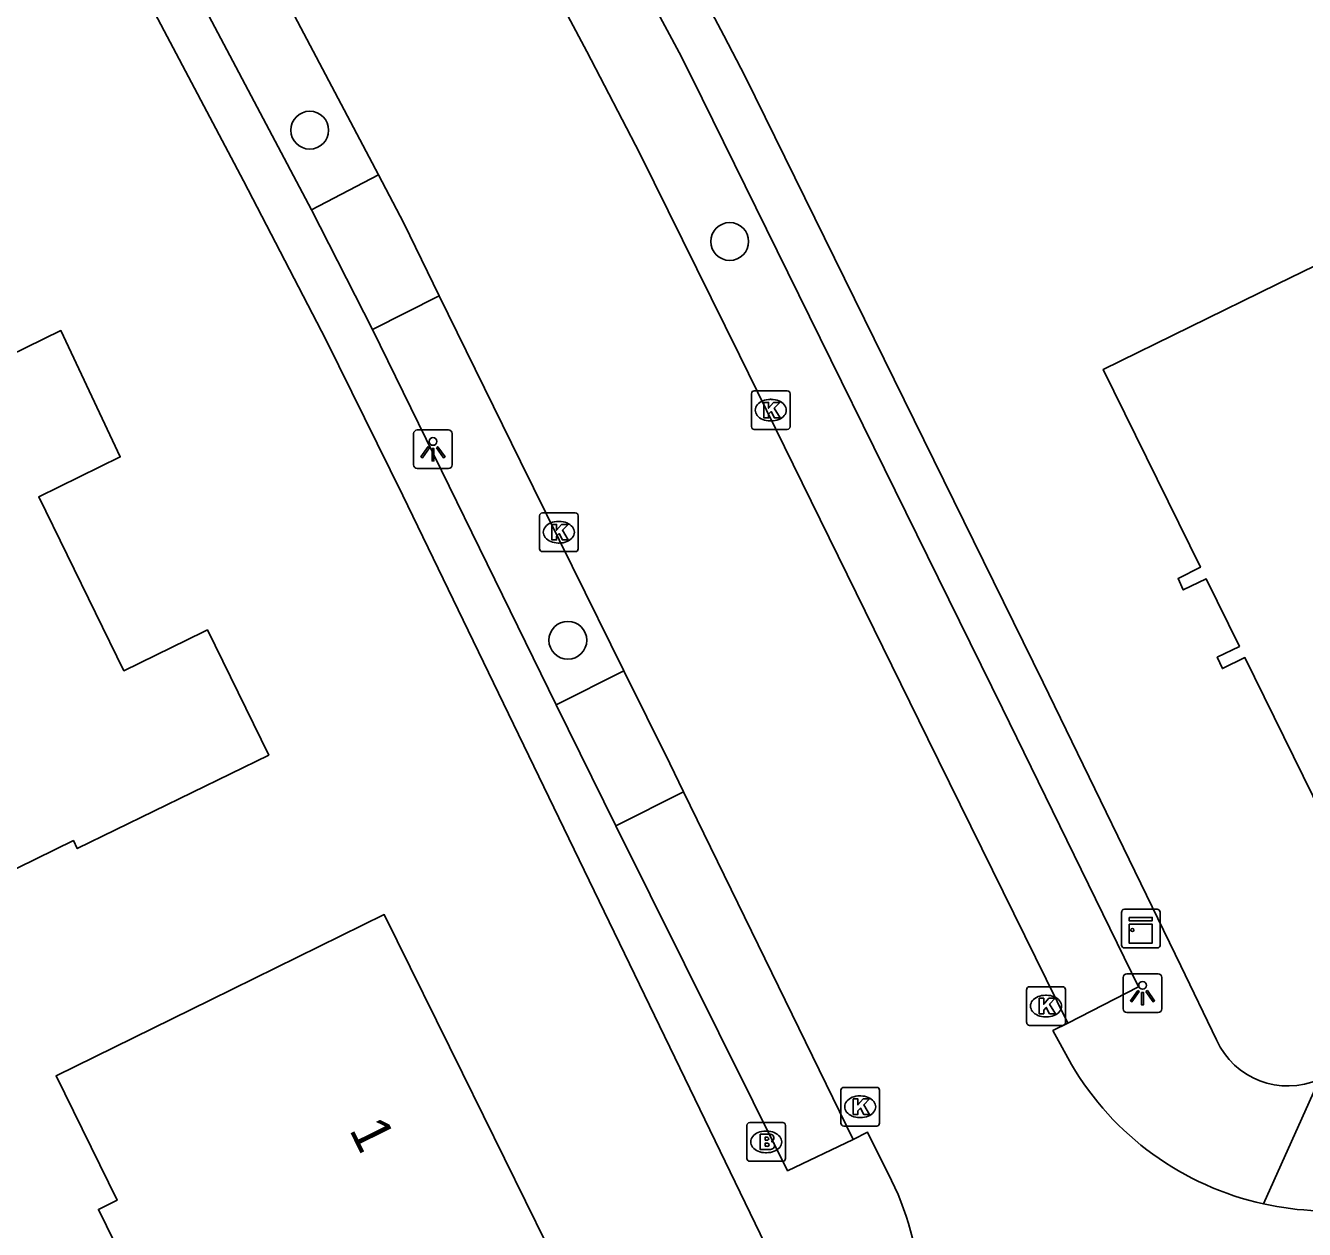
# Model space of a CAD drawing. Extents: x 160457 to 162082, y 388340 to 389736.
# Drawn here: x 160695.95 to 160729, y 389050.96 to 389082.07 of the extents above; entities that cross this region are included whole.
import ezdxf

# ---------------------------------------------------------------- set-up
doc = ezdxf.new("R2010")
doc.units = 0
for name, color, linetype in [('IMGEO_Boom', 7, 'Continuous'), ('IMGEO_Brandkraan', 7, 'Continuous'), ('IMGEO_Kast', 7, 'Continuous'), ('IMGEO_Kolk', 7, 'Continuous'), ('IMGEO_Lichtpunt', 7, 'Continuous'), ('IMGEO_Pand', 7, 'Continuous'), ('IMGEO_Pand_nummerreeks', 7, 'Continuous'), ('IMGEO_Rijbaan_lokaal_gesloten', 7, 'Continuous'), ('IMGEO_Voetpad_open', 7, 'Continuous')]:
    doc.layers.add(name, color=color, linetype=linetype)

msp = doc.modelspace()

# ---------------------------------------------------------------- linework, layer by layer
at = {"layer": 'IMGEO_Boom'}
for centre in [(160703.291, 389079.364), (160714.145, 389076.488), (160709.962, 389066.184)]:
    msp.add_circle(centre, 0.489, dxfattribs=at)
at = {"layer": 'IMGEO_Brandkraan'}
for p, q in [((160714.587, 389052.796), (160714.587, 389053.648)), ((160714.662, 389053.722), (160715.514, 389053.722)), ((160715.075, 389053.502), (160715.1, 389053.502)), ((160715.588, 389053.648), (160715.588, 389052.796)), ((160715.098, 389052.942), (160715.073, 389052.942)), ((160715.514, 389052.722), (160714.662, 389052.722))]:
    msp.add_line(p, q, dxfattribs=at)
for points in [[(160714.587, 389052.796), (160714.587, 389053.648)], [(160714.662, 389053.722), (160715.514, 389053.722)], [(160715.588, 389053.648), (160715.588, 389052.796)], [(160714.935, 389053.422), (160714.935, 389053.022), (160715.148, 389053.022)], [(160715.166, 389053.422), (160714.935, 389053.422)], [(160715.114, 389053.341), (160715.06, 389053.341), (160715.06, 389053.265)], [(160715.06, 389053.265), (160715.113, 389053.265)], [(160715.122, 389053.189), (160715.06, 389053.189), (160715.06, 389053.108)], [(160715.06, 389053.108), (160715.122, 389053.108)], [(160715.514, 389052.722), (160714.662, 389052.722)]]:
    msp.add_lwpolyline(points, dxfattribs=at)
for centre, radius, start, end in [((160714.664, 389053.646), 0.0765, 91.552, 178.448), ((160714.664, 389053.646), 0.0765, 91.552, 178.448), ((160715.512, 389053.646), 0.0765, 1.552, 88.448), ((160715.512, 389053.646), 0.0765, 1.552, 88.448), ((160715.115, 389053.303), 0.0379, 267.8285, 90.9355), ((160715.123, 389053.148), 0.0404, 269.8759, 90.5077), ((160715.17, 389053.277), 0.145, 59.4692, 91.5367), ((160715.195, 389053.324), 0.0922, 285.5137, 58.1501), ((160715.2, 389053.132), 0.105, 301.3115, 78.989), ((160715.154, 389053.273), 0.251, 268.6676, 293.5347), ((160714.664, 389052.798), 0.0765, 181.552, 268.448), ((160714.664, 389052.798), 0.0765, 181.552, 268.448), ((160715.512, 389052.798), 0.0765, 271.552, 358.448), ((160715.512, 389052.798), 0.0765, 271.552, 358.448)]:
    msp.add_arc(centre, radius, start, end, dxfattribs=at)
for centre, major_axis, ratio, start_param, end_param in [((160715.074, 389053.222), (-0.387, 0.002), 0.722429, 4.712389, 7.853982), ((160715.099, 389053.222), (-0.39, 0.002), 0.717154, 1.570796, 4.712389)]:
    msp.add_ellipse(centre, major_axis=major_axis, ratio=ratio, start_param=start_param, end_param=end_param, dxfattribs=at)
at = {"layer": 'IMGEO_Kast'}
for p, q in [((160724.272, 389058.308), (160724.272, 389059.149)), ((160724.272, 389059.149), (160724.272, 389058.308)), ((160724.347, 389059.233), (160725.188, 389059.233)), ((160725.188, 389059.233), (160724.347, 389059.233)), ((160725.272, 389059.158), (160725.272, 389058.317)), ((160725.272, 389058.317), (160725.272, 389059.158)), ((160725.197, 389058.233), (160724.356, 389058.233)), ((160724.356, 389058.233), (160725.197, 389058.233))]:
    msp.add_line(p, q, dxfattribs=at)
for points in [[(160724.467, 389059.023), (160725.067, 389059.023), (160725.067, 389058.938), (160724.467, 389058.938), (160724.467, 389059.023)], [(160724.467, 389058.848), (160725.067, 389058.848), (160725.067, 389058.359), (160724.467, 389058.359), (160724.467, 389058.848)]]:
    msp.add_lwpolyline(points, dxfattribs=at)
msp.add_circle((160724.551, 389058.697), 0.0377, dxfattribs=at)
for centre, start, end in [((160724.35, 389059.155), 92.4484, 184.2845), ((160724.35, 389059.155), 92.4484, 184.2845), ((160725.194, 389059.155), 2.4484, 94.2845), ((160725.194, 389059.155), 2.4484, 94.2845), ((160724.35, 389058.311), 182.4484, 274.2845), ((160724.35, 389058.311), 182.4484, 274.2845), ((160725.194, 389058.311), 272.4484, 4.2845), ((160725.194, 389058.311), 272.4484, 4.2845)]:
    msp.add_arc(centre, 0.0779, start, end, dxfattribs=at)
at = {"layer": 'IMGEO_Kolk'}
for p, q in [((160714.706, 389071.704), (160714.706, 389072.556)), ((160714.781, 389072.63), (160715.633, 389072.63)), ((160715.194, 389072.41), (160715.219, 389072.41)), ((160715.707, 389072.556), (160715.707, 389071.704)), ((160715.217, 389071.85), (160715.192, 389071.85)), ((160715.633, 389071.63), (160714.781, 389071.63)), ((160709.228, 389068.55), (160709.228, 389069.402)), ((160709.303, 389069.476), (160710.155, 389069.476)), ((160710.229, 389069.402), (160710.229, 389068.55)), ((160709.716, 389069.256), (160709.741, 389069.256)), ((160709.739, 389068.696), (160709.714, 389068.696)), ((160710.155, 389068.476), (160709.303, 389068.476)), ((160721.819, 389056.306), (160721.819, 389057.158)), ((160721.894, 389057.232), (160722.746, 389057.232)), ((160722.82, 389057.158), (160722.82, 389056.306)), ((160722.307, 389057.012), (160722.332, 389057.012)), ((160722.33, 389056.452), (160722.305, 389056.452)), ((160722.746, 389056.232), (160721.894, 389056.232)), ((160717.016, 389053.705), (160717.016, 389054.557)), ((160717.091, 389054.631), (160717.943, 389054.631)), ((160718.017, 389054.557), (160718.017, 389053.705)), ((160717.504, 389054.411), (160717.529, 389054.411)), ((160717.527, 389053.851), (160717.502, 389053.851)), ((160717.943, 389053.631), (160717.091, 389053.631))]:
    msp.add_line(p, q, dxfattribs=at)
for points in [[(160714.706, 389071.704), (160714.706, 389072.556)], [(160714.781, 389072.63), (160715.633, 389072.63)], [(160715.027, 389072.33), (160715.15, 389072.33), (160715.15, 389072.179), (160715.28, 389072.33), (160715.444, 389072.33), (160715.298, 389072.179), (160715.451, 389071.93), (160715.299, 389071.93), (160715.214, 389072.094), (160715.15, 389072.027), (160715.15, 389071.93), (160715.027, 389071.93), (160715.027, 389072.33)], [(160715.707, 389072.556), (160715.707, 389071.704)], [(160715.633, 389071.63), (160714.781, 389071.63)], [(160709.228, 389068.55), (160709.228, 389069.402)], [(160709.303, 389069.476), (160710.155, 389069.476)], [(160710.229, 389069.402), (160710.229, 389068.55)], [(160709.549, 389069.176), (160709.672, 389069.176), (160709.672, 389069.025), (160709.802, 389069.176), (160709.966, 389069.176), (160709.82, 389069.025), (160709.973, 389068.776), (160709.821, 389068.776), (160709.736, 389068.94), (160709.672, 389068.873), (160709.672, 389068.776), (160709.549, 389068.776), (160709.549, 389069.176)], [(160710.155, 389068.476), (160709.303, 389068.476)], [(160721.819, 389056.306), (160721.819, 389057.158)], [(160721.894, 389057.232), (160722.746, 389057.232)], [(160722.82, 389057.158), (160722.82, 389056.306)], [(160722.14, 389056.932), (160722.263, 389056.932), (160722.263, 389056.781), (160722.393, 389056.932), (160722.557, 389056.932), (160722.411, 389056.781), (160722.564, 389056.532), (160722.412, 389056.532), (160722.327, 389056.696), (160722.263, 389056.629), (160722.263, 389056.532), (160722.14, 389056.532), (160722.14, 389056.932)], [(160722.746, 389056.232), (160721.894, 389056.232)], [(160717.016, 389053.705), (160717.016, 389054.557)], [(160717.091, 389054.631), (160717.943, 389054.631)], [(160718.017, 389054.557), (160718.017, 389053.705)], [(160717.337, 389054.331), (160717.46, 389054.331), (160717.46, 389054.18), (160717.59, 389054.331), (160717.754, 389054.331), (160717.608, 389054.18), (160717.761, 389053.931), (160717.609, 389053.931), (160717.524, 389054.095), (160717.46, 389054.028), (160717.46, 389053.931), (160717.337, 389053.931), (160717.337, 389054.331)], [(160717.943, 389053.631), (160717.091, 389053.631)]]:
    msp.add_lwpolyline(points, dxfattribs=at)
for centre, start, end in [((160714.783, 389072.554), 91.552, 178.448), ((160714.783, 389072.554), 91.552, 178.448), ((160715.631, 389072.554), 1.552, 88.448), ((160715.631, 389072.554), 1.552, 88.448), ((160714.783, 389071.706), 181.552, 268.448), ((160714.783, 389071.706), 181.552, 268.448), ((160715.631, 389071.706), 271.552, 358.448), ((160715.631, 389071.706), 271.552, 358.448), ((160709.305, 389069.4), 91.552, 178.448), ((160709.305, 389069.4), 91.552, 178.448), ((160710.153, 389069.4), 1.552, 88.448), ((160710.153, 389069.4), 1.552, 88.448), ((160709.305, 389068.552), 181.552, 268.448), ((160709.305, 389068.552), 181.552, 268.448), ((160710.153, 389068.552), 271.552, 358.448), ((160710.153, 389068.552), 271.552, 358.448), ((160721.896, 389057.156), 91.552, 178.448), ((160721.896, 389057.156), 91.552, 178.448), ((160722.744, 389057.156), 1.552, 88.448), ((160722.744, 389057.156), 1.552, 88.448), ((160721.896, 389056.308), 181.552, 268.448), ((160721.896, 389056.308), 181.552, 268.448), ((160722.744, 389056.308), 271.552, 358.448), ((160722.744, 389056.308), 271.552, 358.448), ((160717.093, 389054.555), 91.552, 178.448), ((160717.093, 389054.555), 91.552, 178.448), ((160717.941, 389054.555), 1.552, 88.448), ((160717.941, 389054.555), 1.552, 88.448), ((160717.093, 389053.707), 181.552, 268.448), ((160717.093, 389053.707), 181.552, 268.448), ((160717.941, 389053.707), 271.552, 358.448), ((160717.941, 389053.707), 271.552, 358.448)]:
    msp.add_arc(centre, 0.0765, start, end, dxfattribs=at)
for centre, major_axis, ratio, start_param, end_param in [((160715.193, 389072.13), (-0.387, 0.002), 0.722429, 4.712389, 7.853982), ((160715.218, 389072.13), (-0.39, 0.002), 0.717154, 1.570796, 4.712389), ((160709.715, 389068.976), (-0.387, 0.002), 0.722429, 4.712389, 7.853982), ((160709.74, 389068.976), (-0.39, 0.002), 0.717154, 1.570796, 4.712389), ((160722.306, 389056.732), (-0.387, 0.002), 0.722429, 4.712389, 7.853982), ((160722.331, 389056.732), (-0.39, 0.002), 0.717154, 1.570796, 4.712389), ((160717.503, 389054.131), (-0.387, 0.002), 0.722429, 4.712389, 7.853982), ((160717.528, 389054.131), (-0.39, 0.002), 0.717154, 1.570796, 4.712389)]:
    msp.add_ellipse(centre, major_axis=major_axis, ratio=ratio, start_param=start_param, end_param=end_param, dxfattribs=at)
at = {"layer": 'IMGEO_Lichtpunt'}
for p, q in [((160705.977, 389071.523), (160705.977, 389070.716)), ((160705.977, 389071.523), (160705.977, 389070.716)), ((160706.879, 389071.618), (160706.071, 389071.618)), ((160706.879, 389071.618), (160706.071, 389071.618)), ((160706.973, 389070.716), (160706.973, 389071.523)), ((160706.973, 389070.716), (160706.973, 389071.523)), ((160706.071, 389070.622), (160706.879, 389070.622)), ((160706.071, 389070.622), (160706.879, 389070.622)), ((160724.315, 389057.469), (160724.315, 389056.662)), ((160724.315, 389057.469), (160724.315, 389056.662)), ((160725.217, 389057.564), (160724.409, 389057.564)), ((160725.217, 389057.564), (160724.409, 389057.564)), ((160725.311, 389056.662), (160725.311, 389057.469)), ((160725.311, 389056.662), (160725.311, 389057.469)), ((160724.409, 389056.568), (160725.217, 389056.568)), ((160724.409, 389056.568), (160725.217, 389056.568))]:
    msp.add_line(p, q, dxfattribs=at)
for points in [[(160706.351, 389071.187), (160706.39, 389071.159), (160706.202, 389070.897), (160706.164, 389070.924), (160706.351, 389071.187)], [(160706.453, 389071.139), (160706.5, 389071.139), (160706.5, 389070.817), (160706.453, 389070.817), (160706.453, 389071.139)], [(160706.563, 389071.159), (160706.601, 389071.186), (160706.788, 389070.924), (160706.749, 389070.896), (160706.563, 389071.159)], [(160724.689, 389057.133), (160724.728, 389057.105), (160724.54, 389056.843), (160724.502, 389056.87), (160724.689, 389057.133)], [(160724.901, 389057.105), (160724.939, 389057.132), (160725.126, 389056.87), (160725.087, 389056.842), (160724.901, 389057.105)], [(160724.791, 389057.085), (160724.838, 389057.085), (160724.838, 389056.763), (160724.791, 389056.763), (160724.791, 389057.085)]]:
    msp.add_lwpolyline(points, dxfattribs=at)
for centre in [(160706.476, 389071.321), (160724.814, 389057.267)]:
    msp.add_circle(centre, 0.0994, dxfattribs=at)
for centre, start, end in [((160706.071, 389071.523), 90, 180), ((160706.071, 389071.523), 90, 180), ((160706.879, 389071.523), 0, 90), ((160706.879, 389071.523), 0, 90), ((160706.071, 389070.716), 180, 270), ((160706.071, 389070.716), 180, 270), ((160706.879, 389070.716), 270, 0), ((160706.879, 389070.716), 270, 360), ((160724.409, 389057.469), 90, 180), ((160724.409, 389057.469), 90, 180), ((160725.217, 389057.469), 0, 90), ((160725.217, 389057.469), 0, 90), ((160724.409, 389056.662), 180, 270), ((160724.409, 389056.662), 180, 270), ((160725.217, 389056.662), 270, 0), ((160725.217, 389056.662), 270, 360)]:
    msp.add_arc(centre, 0.0946, start, end, dxfattribs=at)
at = {"layer": 'IMGEO_Pand'}
for points in [[(160740.8, 389072.592), (160742.998, 389068.101), (160737.442, 389065.38), (160737.872, 389064.502), (160729.969, 389060.625), (160727.458, 389065.737), (160726.877, 389065.452), (160726.744, 389065.744), (160727.316, 389066.025), (160726.457, 389067.774), (160725.868, 389067.485), (160725.733, 389067.784), (160726.312, 389068.069), (160723.799, 389073.184), (160728.29, 389075.383), (160730.22, 389076.328), (160731.187, 389074.352), (160738.245, 389077.808), (160740.8, 389072.592)], [(160692.369, 389071.992), (160696.861, 389074.186), (160698.396, 389070.922), (160696.289, 389069.892), (160698.487, 389065.395), (160700.542, 389066.399), (160700.646, 389066.45), (160702.23, 389063.217), (160697.283, 389060.801), (160697.182, 389061.008), (160693.314, 389059.118), (160693.415, 389058.911), (160689.539, 389057.018), (160684.179, 389067.991), (160692.369, 389071.992)], [(160700.731, 389056.893), (160705.219, 389059.096), (160707.239, 389054.997), (160709.412, 389050.587), (160701.805, 389046.867), (160700.23, 389050.075), (160698.85, 389049.397), (160697.83, 389051.476), (160698.313, 389051.713), (160696.734, 389054.93), (160700.731, 389056.893)]]:
    msp.add_lwpolyline(points, dxfattribs=at)
at = {"layer": 'IMGEO_Rijbaan_lokaal_gesloten'}
for points in [[(160722.882, 389056.293), (160719.266, 389063.633), (160714.398, 389073.548), (160711.825, 389078.763), (160710.449, 389081.399), (160705.683, 389090.365), (160705.359, 389090.978)], [(160698.893, 389089.881), (160702.17, 389083.695), (160705.064, 389078.212)], [(160705.064, 389078.212), (160705.723, 389076.964), (160706.64, 389075.087)], [(160706.64, 389075.087), (160708.736, 389070.801), (160711.41, 389065.397)], [(160711.41, 389065.397), (160712.595, 389063.003), (160712.953, 389062.269)], [(160712.953, 389062.269), (160717.338, 389053.28)], [(160722.978, 389055.222), (160722.5, 389056.097), (160722.882, 389056.293)], [(160717.338, 389053.28), (160717.707, 389053.473), (160718.144, 389052.583)]]:
    msp.add_lwpolyline(points, dxfattribs=at)
for centre, radius, start, end in [((160729.566, 389059.084), 7.636, 210.3784, 257.7317), ((160711.704, 389049.006), 7.367, 339.7023, 29.045), ((160729.625, 389059.133), 7.697, 257.3756, 299.0621)]:
    msp.add_arc(centre, radius, start, end, dxfattribs=at)
at = {"layer": 'IMGEO_Voetpad_open'}
for points in [[(160666.197, 389171.948), (160666.685, 389171.014), (160676.789, 389151.881), (160708.027, 389092.962), (160711.74, 389086.082), (160713.992, 389081.813), (160714.548, 389080.749), (160722.246, 389065.089), (160725.803, 389057.769), (160726.725, 389055.856)], [(160715.497, 389049.443), (160715.59, 389049.493), (160705.696, 389069.922), (160703.712, 389073.937), (160701.581, 389078.055), (160687.433, 389104.792), (160673.051, 389131.978), (160665.928, 389145.4), (160655.489, 389165.053), (160655.393, 389165.23)], [(160722.882, 389056.293), (160724.711, 389057.228), (160721.194, 389064.425), (160713.435, 389080.182), (160712.901, 389081.257), (160710.623, 389085.496), (160707.206, 389091.946)], [(160697.171, 389088.966), (160703.333, 389077.308)], [(160703.333, 389077.308), (160705.064, 389078.212)], [(160703.333, 389077.308), (160704.911, 389074.21)], [(160704.911, 389074.21), (160706.64, 389075.087)], [(160704.911, 389074.21), (160709.663, 389064.517)], [(160711.41, 389065.397), (160709.663, 389064.517)], [(160709.663, 389064.517), (160711.199, 389061.393)], [(160711.199, 389061.393), (160712.953, 389062.269)], [(160711.199, 389061.393), (160715.639, 389052.478), (160717.338, 389053.28)], [(160729.384, 389054.841), (160727.943, 389051.622)]]:
    msp.add_lwpolyline(points, dxfattribs=at)
msp.add_arc((160728.568, 389056.693), 2.024, 204.4189, 293.7952, dxfattribs=at)

# ---------------------------------------------------------------- texts
at = {"layer": 'IMGEO_Pand_nummerreeks'}
msp.add_text('1', height=1, rotation=296.2328, dxfattribs=at).set_placement((160704.302, 389053.537))

doc.saveas('drawing.dxf')
